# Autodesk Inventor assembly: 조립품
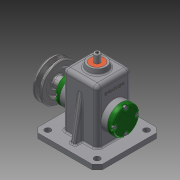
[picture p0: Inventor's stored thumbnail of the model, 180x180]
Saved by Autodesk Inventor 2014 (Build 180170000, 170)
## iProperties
Created: 2016-02
Part Number: 조립품
Document SubType Name: Assembly
Designer: user
Author: user
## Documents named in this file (16)
- C:\Users\user\Desktop\조립품.iam
- C:\Users\user\Desktop\본체.ipt
- C:\Users\user\Desktop\460212V1025.1\V벨트풀리.ipt
- C:\Users\user\Desktop\460212V1025.1\고정핀 1.2 x 10.ipt
- C:\Users\user\Desktop\460212V1025.1\뒤커버.ipt
- C:\Users\user\Desktop\460212V1025.1\링크.ipt
- C:\Users\user\Desktop\460212V1025.1\멈춤나사 M3x8.ipt
- C:\Users\user\Desktop\460212V1025.1\베어링 12 x 32 x 10.ipt
- C:\Users\user\Desktop\460212V1025.1\볼트 M4 x 12.ipt
- C:\Users\user\Desktop\460212V1025.1\부시.ipt
- C:\Users\user\Desktop\460212V1025.1\슬라이드.ipt
- C:\Users\user\Desktop\460212V1025.1\앞커버.ipt
- C:\Users\user\Desktop\460212V1025.1\오일실 12 25 7.ipt
- C:\Users\user\Desktop\460212V1025.1\키 4 x 4 x 10.ipt
- C:\Users\user\Desktop\460212V1025.1\편심축.ipt
- C:\Users\user\Desktop\460212V1025.1\핀 5 x 18.ipt
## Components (11 placed, 4 different names)
1. V벨트풀리:1 — Mate:10, Mate:11, Mate:12
2. 고정핀 1.2 x 10:1 — Rigid:2
3. ISO 4762 M4 x 12:1 — Insert:23
4. 핀 5 x 18:1 — Rigid:2, Insert:24
5. ISO 4762 M4 x 12:2 — Insert:16
6. ISO 4762 M4 x 12:3 — Insert:18
7. ISO 4762 M4 x 12:4 — Insert:19
8. ISO 4762 M4 x 12:5 — Insert:17
9. ISO 4762 M4 x 12:6 — Insert:21
10. ISO 4762 M4 x 12:7 — Insert:22
11. ISO 4762 M4 x 12:8 — Insert:20
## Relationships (13: Insert 9, Mate 3, WeldJoint 1)
- Mate:10: V벨트풀리:1
- Mate:11: V벨트풀리:1
- Mate:12: V벨트풀리:1
- Insert:16: ISO 4762 M4 x 12:2
- Insert:17: ISO 4762 M4 x 12:5
- Insert:18: ISO 4762 M4 x 12:3
- Insert:19: ISO 4762 M4 x 12:4
- Insert:20: ISO 4762 M4 x 12:8
- Insert:21: ISO 4762 M4 x 12:6
- Insert:22: ISO 4762 M4 x 12:7
- Insert:23: ISO 4762 M4 x 12:1
- Rigid:2 [WeldJoint]: 고정핀 1.2 x 10:1 ↔ 핀 5 x 18:1
- Insert:24: 핀 5 x 18:1
